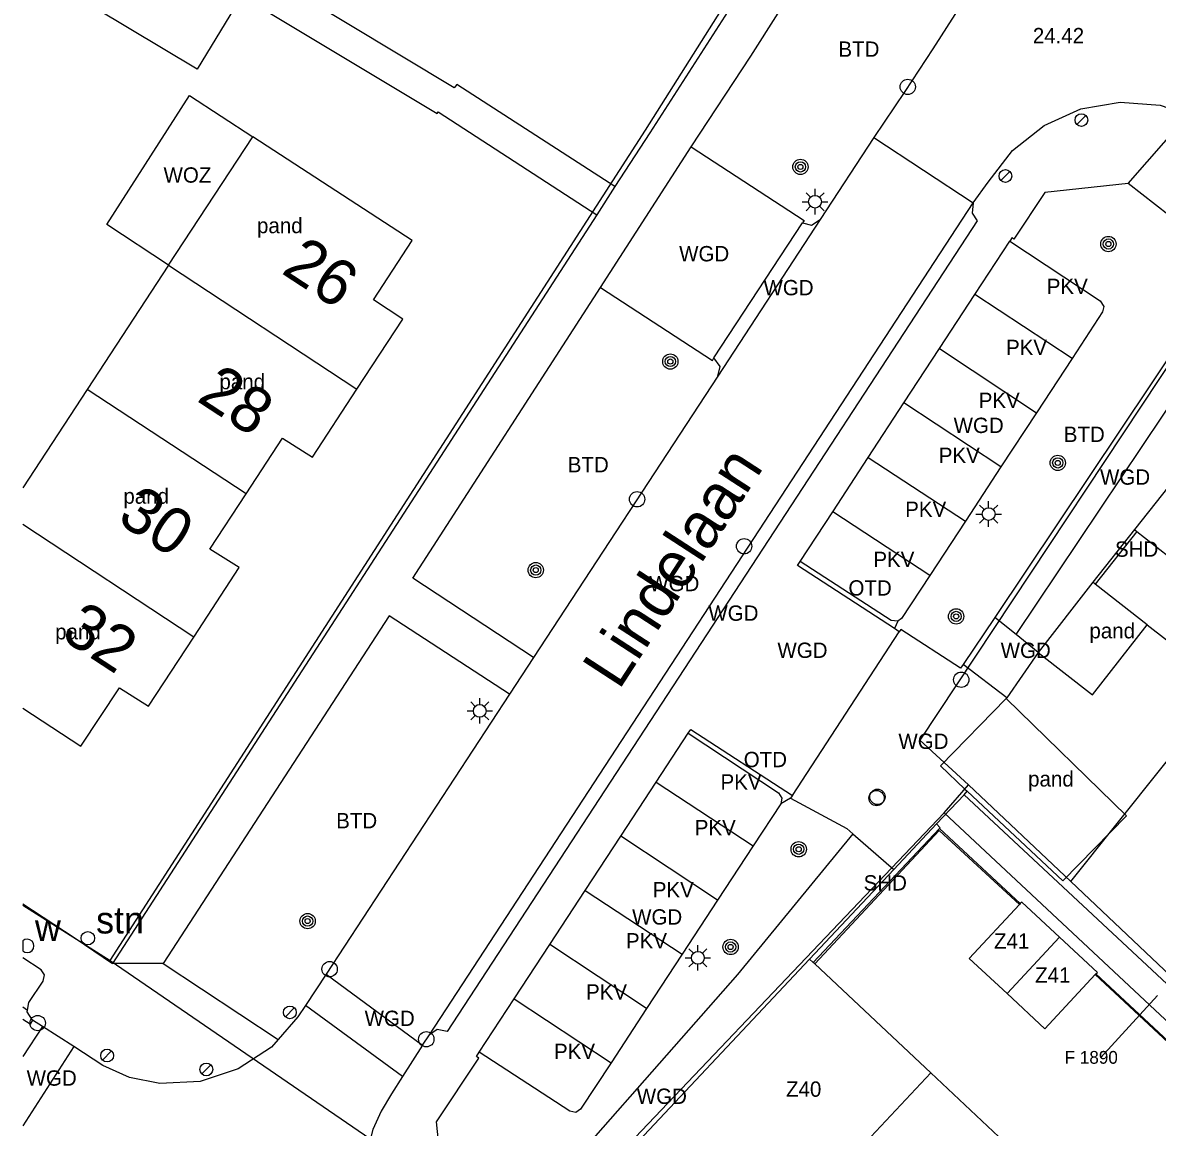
# Model space of a CAD drawing. Extents: x 198240 to 198429, y 356553 to 356721.
# Drawn here: x 198239.79 to 198284.19, y 356586.38 to 356629.62 of the extents above; entities that cross this region are included whole.
import ezdxf

# ---------------------------------------------------------------- set-up
doc = ezdxf.new("R2010")
doc.units = 0
for name, color, linetype in [('Afsluitpaal', 7, 'Continuous'), ('begroeid terreindeel kenmerkpunt', 7, 'Continuous'), ('bijgebouw', 7, 'Continuous'), ('bijpijling', 7, 'Continuous'), ('BOOM', 7, 'Continuous'), ('Grens beheer openbare ruimte', 7, 'Continuous'), ('Grens beheer openbare ruimte wegbeheer', 7, 'Continuous'), ('grens individueel parkeervak', 7, 'Continuous'), ('Grens maaiveld', 7, 'Continuous'), ('grens WOZ object', 7, 'Continuous'), ('hoofdgebouw', 7, 'Continuous'), ('Hoogtepunt', 7, 'Continuous'), ('huisnummerreeks BGT', 7, 'Continuous'), ('identificerend kenmerkpunt bijpand', 7, 'Continuous'), ('identificerend kenmerkpunt pand', 7, 'Continuous'), ('identificerend kenmerkpunt parkeervak', 7, 'Continuous'), ('identificerend kenmerkpunt WOZ object', 7, 'Continuous'), ('kant verharding', 7, 'Continuous'), ('kolk', 7, 'Continuous'), ('LICHTMAST', 7, 'Continuous'), ('muur breder dan 30cm', 7, 'Continuous'), ('onbegroeid terreindeel kenmerkpunt', 7, 'Continuous'), ('openbare ruimte label tekst', 7, 'Continuous'), ('Perceelnummer', 7, 'Continuous'), ('perceelsgrens_definitief', 7, 'Continuous'), ('scheiding kenmerkpunt', 7, 'Continuous'), ('schutting geen IMGeo', 7, 'Continuous'), ('straatnaambord', 7, 'Continuous'), ('tussenmuur', 7, 'Continuous'), ('tussenmuur bijgebouw (GBKN Zuid)', 7, 'Continuous'), ('vlakafsluiter', 7, 'Continuous'), ('waterleidingput', 7, 'Continuous'), ('wegdeel kenmerkpunt', 7, 'Continuous'), ('weginrichtingselement lijn', 7, 'Continuous')]:
    doc.layers.add(name, color=color, linetype=linetype)

msp = doc.modelspace()

# ---------------------------------------------------------------- linework, layer by layer
at = {"layer": 'Afsluitpaal'}
for p, q in [((198281.398, 356625.987), (198281.048, 356625.63)), ((198278.423, 356623.798), (198278.073, 356623.441)), ((198250.417, 356591.058), (198250.067, 356590.701)), ((198243.265, 356589.372), (198242.915, 356589.015)), ((198247.147, 356588.826), (198246.797, 356588.469))]:
    msp.add_line(p, q, dxfattribs=at)
for centre in [(198281.225, 356625.807), (198278.25, 356623.618), (198250.244, 356590.878), (198243.092, 356589.192), (198246.974, 356588.646)]:
    msp.add_circle(centre, 0.25, dxfattribs=at)
at = {"layer": 'bijgebouw'}
for p, q in [((198281.673, 356607.714), (198279.53, 356604.971)), ((198281.765, 356607.642), (198281.673, 356607.714)), ((198283.799, 356606.053), (198281.765, 356607.642)), ((198276.665, 356599.624), (198276.758, 356599.537)), ((198278.83, 356595.136), (198278.8, 356595.104)), ((198281.768, 356592.361), (198281.792, 356592.387))]:
    msp.add_line(p, q, dxfattribs=at)
for points in [[(198241.348, 356634.089), (198241.602, 356634.513), (198248.255, 356630.521), (198246.617, 356627.795), (198239.968, 356631.79)], [(198279.53, 356604.971), (198281.659, 356603.31), (198283.799, 356606.053)], [(198278.285, 356603.168), (198275.704, 356600.528), (198276.665, 356599.624)], [(198276.758, 356599.537), (198280.493, 356596.024), (198282.99, 356598.568), (198278.285, 356603.168)], [(198278.8, 356595.104), (198276.834, 356592.99), (198278.313, 356591.614)], [(198280.37, 356593.825), (198278.891, 356595.201), (198278.83, 356595.136)], [(198281.792, 356592.387), (198281.849, 356592.448), (198280.37, 356593.825)], [(198278.313, 356591.614), (198279.792, 356590.237), (198281.768, 356592.361)]]:
    msp.add_lwpolyline(points, dxfattribs=at)
at = {"layer": 'bijpijling'}
msp.add_lwpolyline([(198284.2, 356591.537), (198281.985, 356589.12)], dxfattribs=at)
at = {"layer": 'BOOM'}
for centre, radius in [((198270.227, 356623.975), 0.3), ((198270.227, 356623.975), 0.2), ((198270.227, 356623.975), 0.1), ((198282.279, 356620.957), 0.3), ((198282.279, 356620.957), 0.2), ((198282.279, 356620.957), 0.1), ((198265.135, 356616.356), 0.3), ((198265.135, 356616.356), 0.2), ((198265.135, 356616.356), 0.1), ((198280.298, 356612.389), 0.3), ((198280.298, 356612.389), 0.2), ((198280.298, 356612.389), 0.1), ((198259.867, 356608.193), 0.3), ((198259.867, 356608.193), 0.2), ((198259.867, 356608.193), 0.1), ((198276.321, 356606.381), 0.3), ((198276.321, 356606.381), 0.2), ((198276.321, 356606.381), 0.1), ((198270.158, 356597.265), 0.3), ((198270.158, 356597.265), 0.2), ((198270.158, 356597.265), 0.1), ((198250.94, 356594.454), 0.3), ((198250.94, 356594.454), 0.2), ((198250.94, 356594.454), 0.1), ((198267.495, 356593.44), 0.3), ((198267.495, 356593.44), 0.2), ((198267.495, 356593.44), 0.1)]:
    msp.add_circle(centre, radius, dxfattribs=at)
at = {"layer": 'Grens beheer openbare ruimte'}
for p, q in [((198275.556, 356598.257), (198276.632, 356599.402)), ((198276.632, 356599.402), (198276.758, 356599.537))]:
    msp.add_line(p, q, dxfattribs=at)
at = {"layer": 'Grens beheer openbare ruimte wegbeheer'}
msp.add_line((198241.788, 356589.543), (198239.787, 356586.445), dxfattribs=at)
at = {"layer": 'grens individueel parkeervak'}
for p, q in [((198280.856, 356616.477), (198277.052, 356618.98)), ((198275.668, 356616.864), (198279.462, 356614.348)), ((198278.076, 356612.232), (198274.275, 356614.734)), ((198272.882, 356612.605), (198276.683, 356610.104)), ((198275.295, 356607.984), (198271.49, 356610.477)), ((198264.579, 356599.893), (198268.378, 356597.403)), ((198266.986, 356595.277), (198263.195, 356597.78)), ((198261.802, 356595.655), (198265.601, 356593.16)), ((198264.207, 356591.032), (198260.413, 356593.535)), ((198259.022, 356591.413), (198262.817, 356588.908))]:
    msp.add_line(p, q, dxfattribs=at)
at = {"layer": 'Grens maaiveld'}
for p, q in [((198273.106, 356625.127), (198276.992, 356622.565)), ((198262.4, 356619.255), (198265.95, 356624.757)), ((198279.53, 356604.971), (198278.305, 356603.189)), ((198278.305, 356603.189), (198278.285, 356603.168)), ((198251.667, 356592.381), (198255.434, 356589.602)), ((198254.653, 356588.377), (198250.852, 356591.155)), ((198240.558, 356590.331), (198239.787, 356589.149))]:
    msp.add_line(p, q, dxfattribs=at)
for points in [[(198272.277, 356597.868), (198267.761, 356592.361), (198258.856, 356582.232)], [(198240.176, 356590.575), (198240.077, 356590.415), (198239.787, 356590.603)]]:
    msp.add_lwpolyline(points, dxfattribs=at)
at = {"layer": 'grens WOZ object'}
msp.add_line((198283.799, 356606.053), (198286.719, 356603.776), dxfattribs=at)
msp.add_lwpolyline([(198245.494, 356620.123), (198243.078, 356621.72), (198246.319, 356626.768), (198248.789, 356625.152)], dxfattribs=at)
at = {"layer": 'hoofdgebouw'}
for p, q in [((198245.494, 356620.123), (198248.789, 356625.152)), ((198245.494, 356620.123), (198242.31, 356615.264)), ((198287.746, 356615.433), (198283.304, 356609.78)), ((198242.31, 356615.264), (198239.787, 356611.414)), ((198283.304, 356609.78), (198283.398, 356609.706)), ((198283.398, 356609.706), (198288.287, 356605.835)), ((198270.731, 356592.831), (198270.587, 356592.966)), ((198270.785, 356592.78), (198270.731, 356592.831)), ((198275.335, 356588.51), (198270.785, 356592.78)), ((198279.929, 356584.199), (198275.335, 356588.51))]:
    msp.add_line(p, q, dxfattribs=at)
for points in [[(198252.87, 356615.276), (198254.666, 356618.02), (198253.515, 356618.768), (198255.032, 356621.097), (198248.789, 356625.152)], [(198248.531, 356611.176), (198249.959, 356613.353), (198251.128, 356612.613), (198252.87, 356615.276)], [(198246.485, 356605.57), (198248.263, 356608.29), (198247.115, 356609.017), (198248.531, 356611.176)], [(198239.787, 356602.789), (198242.057, 356601.306), (198243.575, 356603.59), (198244.717, 356602.865), (198246.485, 356605.57)], [(198270.587, 356592.966), (198262.695, 356584.566), (198262.699, 356584.562)]]:
    msp.add_lwpolyline(points, dxfattribs=at)
at = {"layer": 'kant verharding'}
for p, q in [((198273.106, 356625.127), (198271.001, 356621.911)), ((198287.334, 356619.961), (198283.058, 356623.324)), ((198262.967, 356623.203), (198262.254, 356622.101)), ((198255.704, 356590), (198276.992, 356622.565)), ((198262.254, 356622.101), (198243.3, 356592.795)), ((198266.844, 356616.495), (198270.312, 356621.788)), ((198271.001, 356621.911), (198266.993, 356615.788)), ((198277.052, 356618.98), (198278.421, 356621.073)), ((198275.668, 356616.864), (198277.052, 356618.98)), ((198285.231, 356617.401), (198277.829, 356606.337)), ((198274.275, 356614.734), (198275.668, 356616.864)), ((198280.856, 356616.477), (198279.462, 356614.348)), ((198266.993, 356615.788), (198259.782, 356604.773)), ((198272.882, 356612.605), (198274.275, 356614.734)), ((198279.462, 356614.348), (198278.076, 356612.232)), ((198271.49, 356610.477), (198272.882, 356612.605)), ((198278.076, 356612.232), (198276.683, 356610.104)), ((198270.219, 356608.534), (198271.49, 356610.477)), ((198276.683, 356610.104), (198275.295, 356607.984)), ((198277.829, 356606.337), (198276.598, 356604.497)), ((198278.665, 356605.666), (198277.829, 356606.337)), ((198274.094, 356605.777), (198273.903, 356605.902)), ((198279.53, 356604.971), (198278.665, 356605.666)), ((198259.782, 356604.773), (198258.843, 356603.338)), ((198278.305, 356603.189), (198276.598, 356604.497)), ((198258.843, 356603.338), (198251.667, 356592.381)), ((198264.579, 356599.893), (198265.829, 356601.805)), ((198263.195, 356597.78), (198264.579, 356599.893)), ((198269.912, 356599.375), (198269.838, 356599.261)), ((198269.456, 356599.049), (198268.378, 356597.403)), ((198278.83, 356595.136), (198275.667, 356598.074)), ((198261.802, 356595.655), (198263.195, 356597.78)), ((198272.277, 356597.868), (198273.877, 356596.469)), ((198268.378, 356597.403), (198266.986, 356595.277)), ((198260.413, 356593.535), (198261.802, 356595.655)), ((198266.986, 356595.277), (198265.601, 356593.16)), ((198259.022, 356591.413), (198260.413, 356593.535)), ((198265.601, 356593.16), (198264.207, 356591.032)), ((198245.284, 356592.792), (198249.782, 356589.816)), ((198251.667, 356592.381), (198250.852, 356591.155)), ((198288.036, 356586.564), (198281.792, 356592.387)), ((198257.648, 356589.317), (198259.022, 356591.413)), ((198264.207, 356591.032), (198262.817, 356588.908)), ((198240.558, 356590.331), (198240.176, 356590.575)), ((198241.788, 356589.543), (198240.558, 356590.331)), ((198255.434, 356589.602), (198255.704, 356590)), ((198255.434, 356589.602), (198254.653, 356588.377))]:
    msp.add_line(p, q, dxfattribs=at)
for points in [[(198298.672, 356681.879), (198281.729, 356652.893), (198280.805, 356651.439), (198272.725, 356638.444), (198270.553, 356635.006), (198264.327, 356625.306), (198262.967, 356623.203)], [(198262.967, 356623.203), (198256.774, 356627.2), (198256.672, 356627.069), (198239.787, 356637.236)], [(198239.787, 356635.812), (198256.01, 356626.063), (198256.042, 356626.133), (198262.254, 356622.101)], [(198265.95, 356624.757), (198268.291, 356628.312), (198269.36, 356629.996), (198270.462, 356631.678), (198272.546, 356634.962), (198277.462, 356631.806)], [(198277.462, 356631.806), (198275.413, 356628.597), (198274.312, 356626.921), (198273.106, 356625.127)], [(198276.992, 356622.565), (198277.573, 356623.379), (198278.532, 356624.618), (198279.766, 356625.596), (198281.202, 356626.245), (198282.742, 356626.511), (198284.311, 356626.387), (198285.402, 356626.015)], [(198265.95, 356624.757), (198270.371, 356621.883), (198270.312, 356621.788)], [(198283.058, 356623.324), (198279.789, 356622.971), (198278.585, 356621.147), (198278.511, 356621.21), (198278.421, 356621.073)], [(198276.992, 356622.565), (198276.942, 356622.162), (198277.149, 356621.864), (198256.397, 356590.138), (198256.006, 356590.208), (198255.704, 356590)], [(198270.312, 356621.788), (198270.664, 356621.697), (198271.001, 356621.911)], [(198278.421, 356621.073), (198281.963, 356618.729), (198282.1, 356618.517), (198282.054, 356618.307), (198280.856, 356616.477)], [(198259.782, 356604.773), (198255.055, 356607.876), (198262.4, 356619.255)], [(198262.4, 356619.255), (198266.785, 356616.403), (198266.844, 356616.495)], [(198278.665, 356605.666), (198286.066, 356616.715), (198285.231, 356617.401)], [(198266.993, 356615.788), (198267.079, 356616.166), (198266.844, 356616.495)], [(198273.903, 356605.902), (198270.115, 356608.375), (198270.219, 356608.534)], [(198274.039, 356606.192), (198273.778, 356606.224), (198270.219, 356608.534)], [(198275.295, 356607.984), (198274.188, 356606.294), (198274.039, 356606.192)], [(198258.843, 356603.338), (198254.133, 356606.405), (198245.284, 356592.792)], [(198276.598, 356604.497), (198276.498, 356604.348), (198274.156, 356605.87), (198274.094, 356605.777)], [(198265.829, 356601.805), (198265.931, 356601.955), (198269.912, 356599.375)], [(198265.829, 356601.805), (198269.371, 356599.474), (198269.499, 356599.27), (198269.456, 356599.049)], [(198322.703, 356553.702), (198305.854, 356572.145), (198276.632, 356599.402)], [(198269.838, 356599.261), (198272.044, 356598.072), (198272.277, 356597.868)], [(198239.787, 356595.134), (198240.167, 356594.887), (198241.839, 356593.779), (198243.3, 356592.795)], [(198239.976, 356590.973), (198240.033, 356591.27), (198240.59, 356592.104), (198240.642, 356592.346), (198240.506, 356592.541), (198239.787, 356593.018)], [(198239.787, 356591.097), (198239.976, 356590.973)], [(198240.176, 356590.575), (198239.962, 356590.897), (198239.976, 356590.973)], [(198250.852, 356591.155), (198250.557, 356590.71), (198249.782, 356589.816)], [(198249.782, 356589.816), (198249.53, 356589.525), (198248.215, 356588.667), (198246.731, 356588.179), (198245.16, 356588.092), (198243.973, 356588.333), (198242.924, 356588.795), (198241.788, 356589.543)], [(198256.055, 356585.841), (198255.989, 356586.59), (198257.636, 356589.092), (198257.545, 356589.159), (198257.648, 356589.317)], [(198262.817, 356588.908), (198261.625, 356587.088), (198261.441, 356586.961), (198261.201, 356587.008), (198257.648, 356589.317)], [(198254.653, 356588.377), (198254.218, 356587.696), (198253.817, 356587.017), (198253.496, 356586.295), (198253.293, 356585.524), (198253.233, 356584.742), (198253.288, 356583.945), (198253.466, 356583.177), (198253.779, 356582.443), (198254.159, 356581.761), (198254.551, 356581.262)]]:
    msp.add_lwpolyline(points, dxfattribs=at)
at = {"layer": 'kolk'}
for centre in [(198274.428, 356627.108), (198263.834, 356610.965), (198268.022, 356609.124), (198276.521, 356603.902), (198273.206, 356599.269), (198273.24, 356599.318), (198251.8, 356592.572), (198240.374, 356590.462), (198255.585, 356589.828)]:
    msp.add_circle(centre, 0.3, dxfattribs=at)
at = {"layer": 'LICHTMAST'}
for p, q in [((198270.622, 356622.789), (198270.445, 356622.966)), ((198270.799, 356622.862), (198270.799, 356623.112)), ((198270.976, 356622.789), (198271.153, 356622.966)), ((198270.299, 356622.612), (198270.549, 356622.612)), ((198270.445, 356622.258), (198270.622, 356622.435)), ((198271.153, 356622.258), (198270.976, 356622.435)), ((198271.049, 356622.612), (198271.299, 356622.612)), ((198270.799, 356622.112), (198270.799, 356622.362)), ((198277.593, 356610.636), (198277.593, 356610.886)), ((198277.416, 356610.563), (198277.239, 356610.74)), ((198277.77, 356610.563), (198277.947, 356610.74)), ((198277.093, 356610.386), (198277.343, 356610.386)), ((198277.239, 356610.032), (198277.416, 356610.209)), ((198277.593, 356609.886), (198277.593, 356610.136)), ((198277.947, 356610.032), (198277.77, 356610.209)), ((198277.843, 356610.386), (198278.093, 356610.386)), ((198257.5, 356602.86), (198257.323, 356603.037)), ((198257.677, 356602.933), (198257.677, 356603.183)), ((198257.854, 356602.86), (198258.031, 356603.037)), ((198257.177, 356602.683), (198257.427, 356602.683)), ((198257.323, 356602.329), (198257.5, 356602.506)), ((198257.677, 356602.183), (198257.677, 356602.433)), ((198258.031, 356602.329), (198257.854, 356602.506)), ((198257.927, 356602.683), (198258.177, 356602.683)), ((198266.036, 356593.193), (198265.859, 356593.37)), ((198266.213, 356593.266), (198266.213, 356593.516)), ((198266.39, 356593.193), (198266.567, 356593.37)), ((198265.713, 356593.016), (198265.963, 356593.016)), ((198265.859, 356592.662), (198266.036, 356592.839)), ((198266.213, 356592.516), (198266.213, 356592.766)), ((198266.567, 356592.662), (198266.39, 356592.839)), ((198266.463, 356593.016), (198266.713, 356593.016))]:
    msp.add_line(p, q, dxfattribs=at)
for centre in [(198270.799, 356622.612), (198277.593, 356610.386), (198257.677, 356602.683), (198266.213, 356593.016)]:
    msp.add_circle(centre, 0.25, dxfattribs=at)
at = {"layer": 'muur breder dan 30cm'}
for p, q in [((198283.304, 356609.78), (198281.673, 356607.714)), ((198283.398, 356609.706), (198281.765, 356607.642)), ((198270.731, 356592.831), (198275.667, 356598.074)), ((198275.556, 356598.257), (198273.877, 356596.469)), ((198273.877, 356596.469), (198270.587, 356592.966))]:
    msp.add_line(p, q, dxfattribs=at)
msp.add_lwpolyline([(198275.667, 356598.074), (198275.697, 356598.106), (198275.556, 356598.257)], dxfattribs=at)
at = {"layer": 'perceelsgrens_definitief'}
for points in [[(198243.211, 356592.912), (198264.167, 356625.417), (198275.594, 356643.523), (198286.547, 356661.91), (198298.205, 356681.89)], [(198287.174, 356620.057), (198274.894, 356601.537), (198276.811, 356599.792)], [(198280.812, 356596.003), (198295.051, 356613.842)], [(198275.847, 356598.687), (198276.811, 356599.792)], [(198276.811, 356599.792), (198280.812, 356596.003)], [(198259.64, 356581.648), (198275.847, 356598.687)], [(198275.847, 356598.687), (198293.958, 356581.762), (198299.047, 356577.045), (198300.934, 356575.281), (198303.1, 356573.036), (198305.083, 356571.014), (198307.527, 356568.392), (198311.848, 356563.616), (198317.236, 356557.707), (198320.88, 356553.702)], [(198280.812, 356596.003), (198285.695, 356591.384)], [(198239.787, 356595.075), (198243.211, 356592.912)], [(198243.211, 356592.912), (198259.64, 356581.648)]]:
    msp.add_lwpolyline(points, dxfattribs=at)
at = {"layer": 'schutting geen IMGeo'}
msp.add_line((198288.004, 356586.53), (198281.768, 356592.361), dxfattribs=at)
msp.add_lwpolyline([(198278.8, 356595.104), (198275.651, 356597.998), (198270.785, 356592.78)], dxfattribs=at)
at = {"layer": 'straatnaambord'}
msp.add_circle((198242.337, 356593.784), 0.263, dxfattribs=at)
msp.add_circle((198242.337, 356593.784), 0.263, dxfattribs=at)
at = {"layer": 'tussenmuur'}
for p, q in [((198245.494, 356620.123), (198252.87, 356615.276)), ((198248.531, 356611.176), (198242.31, 356615.264)), ((198246.485, 356605.57), (198239.787, 356609.972)), ((198267.436, 356580.11), (198275.335, 356588.51))]:
    msp.add_line(p, q, dxfattribs=at)
at = {"layer": 'tussenmuur bijgebouw (GBKN Zuid)'}
msp.add_line((198280.37, 356593.825), (198278.313, 356591.614), dxfattribs=at)
at = {"layer": 'vlakafsluiter'}
for p, q in [((198283.058, 356623.324), (198285.402, 356626.015)), ((198274.039, 356606.192), (198273.903, 356605.902)), ((198269.912, 356599.375), (198274.094, 356605.777)), ((198269.838, 356599.261), (198269.456, 356599.049)), ((198245.284, 356592.792), (198243.3, 356592.795))]:
    msp.add_line(p, q, dxfattribs=at)
at = {"layer": 'waterleidingput'}
msp.add_line((198239.787, 356593.676), (198239.787, 356593.286), dxfattribs=at)
msp.add_line((198239.787, 356593.676), (198239.787, 356593.286), dxfattribs=at)
msp.add_arc((198239.963, 356593.481), 0.263, 228.0184, 131.9816, dxfattribs=at)
msp.add_arc((198239.963, 356593.481), 0.263, 228.0184, 131.9816, dxfattribs=at)
at = {"layer": 'weginrichtingselement lijn'}
msp.add_lwpolyline([(198240.176, 356590.575), (198240.077, 356590.415), (198239.787, 356590.603)], dxfattribs=at)

# ---------------------------------------------------------------- texts
at = {"layer": 'begroeid terreindeel kenmerkpunt'}
for p in [(198271.714, 356628.285), (198280.534, 356613.208), (198261.121, 356612.02), (198252.057, 356598.085)]:
    msp.add_text('BTD', height=0.6, dxfattribs=at).set_placement(p)
at = {"layer": 'Hoogtepunt'}
msp.add_text('24.42', height=0.6, dxfattribs=at).set_placement((198279.322, 356628.814))
msp.add_text('24.42', height=0.6, dxfattribs=at).set_placement((198279.322, 356628.814))
at = {"layer": 'huisnummerreeks BGT'}
for s, p in [('26', (198249.865, 356619.84)), ('28', (198246.557, 356614.838)), ('30', (198243.428, 356610.103)), ('32', (198241.224, 356605.554))]:
    msp.add_text(s, height=1.8, rotation=326.8, dxfattribs=at).set_placement(p)
at = {"layer": 'identificerend kenmerkpunt bijpand'}
for s, p in [('pand', (198281.538, 356605.52)), ('pand', (198279.138, 356599.72)), ('Z41', (198277.803, 356593.373)), ('Z41', (198279.411, 356592.039))]:
    msp.add_text(s, height=0.6, dxfattribs=at).set_placement(p)
at = {"layer": 'identificerend kenmerkpunt pand'}
for s, p in [('pand', (198248.958, 356621.38)), ('pand', (198247.488, 356615.27)), ('pand', (198243.728, 356610.79)), ('pand', (198241.058, 356605.48)), ('Z40', (198269.663, 356587.578))]:
    msp.add_text(s, height=0.6, dxfattribs=at).set_placement(p)
at = {"layer": 'identificerend kenmerkpunt parkeervak'}
for p in [(198279.868, 356618.997), (198278.274, 356616.608), (198277.204, 356614.538), (198275.642, 356612.386), (198274.328, 356610.275), (198273.081, 356608.311), (198267.101, 356599.602), (198266.091, 356597.816), (198264.448, 356595.381), (198263.398, 356593.382), (198261.836, 356591.383), (198260.581, 356589.052)]:
    msp.add_text('PKV', height=0.6, dxfattribs=at).set_placement(p)
at = {"layer": 'identificerend kenmerkpunt WOZ object'}
msp.add_text('WOZ', height=0.6, dxfattribs=at).set_placement((198245.3, 356623.358))
at = {"layer": 'onbegroeid terreindeel kenmerkpunt'}
for p in [(198272.106, 356607.195), (198268.008, 356600.478)]:
    msp.add_text('OTD', height=0.6, dxfattribs=at).set_placement(p)
at = {"layer": 'openbare ruimte label tekst'}
msp.add_text('Lindelaan', height=1.8, rotation=57, dxfattribs=at).set_placement((198263.123, 356603.466))
at = {"layer": 'Perceelnummer'}
msp.add_text('F 1890', height=0.5, dxfattribs=at).set_placement((198280.568, 356588.87))
at = {"layer": 'scheiding kenmerkpunt'}
for p in [(198282.538, 356608.715), (198272.7, 356595.651)]:
    msp.add_text('SHD', height=0.6, dxfattribs=at).set_placement(p)
at = {"layer": 'straatnaambord'}
msp.add_text('stn', height=1.05, dxfattribs=at).set_placement((198242.661, 356593.969))
at = {"layer": 'waterleidingput'}
msp.add_text('w', height=1.05, dxfattribs=at).set_placement((198240.267, 356593.679))
at = {"layer": 'wegdeel kenmerkpunt'}
for p in [(198265.479, 356620.278), (198268.781, 356618.949), (198276.222, 356613.559), (198281.952, 356611.536), (198264.309, 356607.367), (198266.623, 356606.209), (198269.326, 356604.755), (198278.064, 356604.753), (198274.061, 356601.193), (198263.639, 356594.316), (198253.17, 356590.347), (198239.942, 356588.011), (198263.822, 356587.297)]:
    msp.add_text('WGD', height=0.6, dxfattribs=at).set_placement(p)

doc.saveas('drawing.dxf')
